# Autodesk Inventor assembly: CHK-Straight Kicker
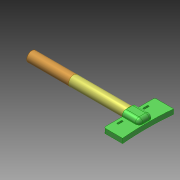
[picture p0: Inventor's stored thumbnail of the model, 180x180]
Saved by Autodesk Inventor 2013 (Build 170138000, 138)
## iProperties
Created: 2013-03
Part Number: CHK-Straight Kicker
Document SubType Name: Assembly
Designer: rYan
Author: rYan
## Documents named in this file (4)
- E:\Tigers SVN\mechanik\2013\Inventor\Checks\CHK-Straight Kicker.iam
- E:\Tigers SVN\mechanik\2013\Inventor\Kicker\Straight\Kicker Stoessel.ipt
- E:\Tigers SVN\mechanik\2013\Inventor\Kicker\Straight\Kicker Mitte.ipt
- E:\Tigers SVN\mechanik\2013\Inventor\Kicker\Straight\Kicker Vorne.ipt
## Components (3 placed, 3 different names)
1. Kicker Stößel:1 — Mate:1, Mate:3
2. Kicker Mitte:1 — Mate:1, Mate:2, Mate:3, Mate:4
3. Kicker Vorne:1 — Mate:2, Mate:4, Angle:1
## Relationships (5: Mate 4, Angle 1)
- Mate:1: Kicker Stößel:1 ↔ Kicker Mitte:1
- Mate:2: Kicker Mitte:1 ↔ Kicker Vorne:1
- Mate:3: Kicker Stößel:1 ↔ Kicker Mitte:1
- Mate:4: Kicker Mitte:1 ↔ Kicker Vorne:1
- Angle:1: Kicker Vorne:1
